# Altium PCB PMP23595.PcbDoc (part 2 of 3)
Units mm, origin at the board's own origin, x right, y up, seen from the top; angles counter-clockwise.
Board outline 121.92 x 78.74 mm, 6 copper layers (Layer 1, GND 1, Layer 3, Layer 4, GND 2, Layer 6), stack 2.208 mm thick; 236 components, 76 nets, 570 pads, 735 vias.
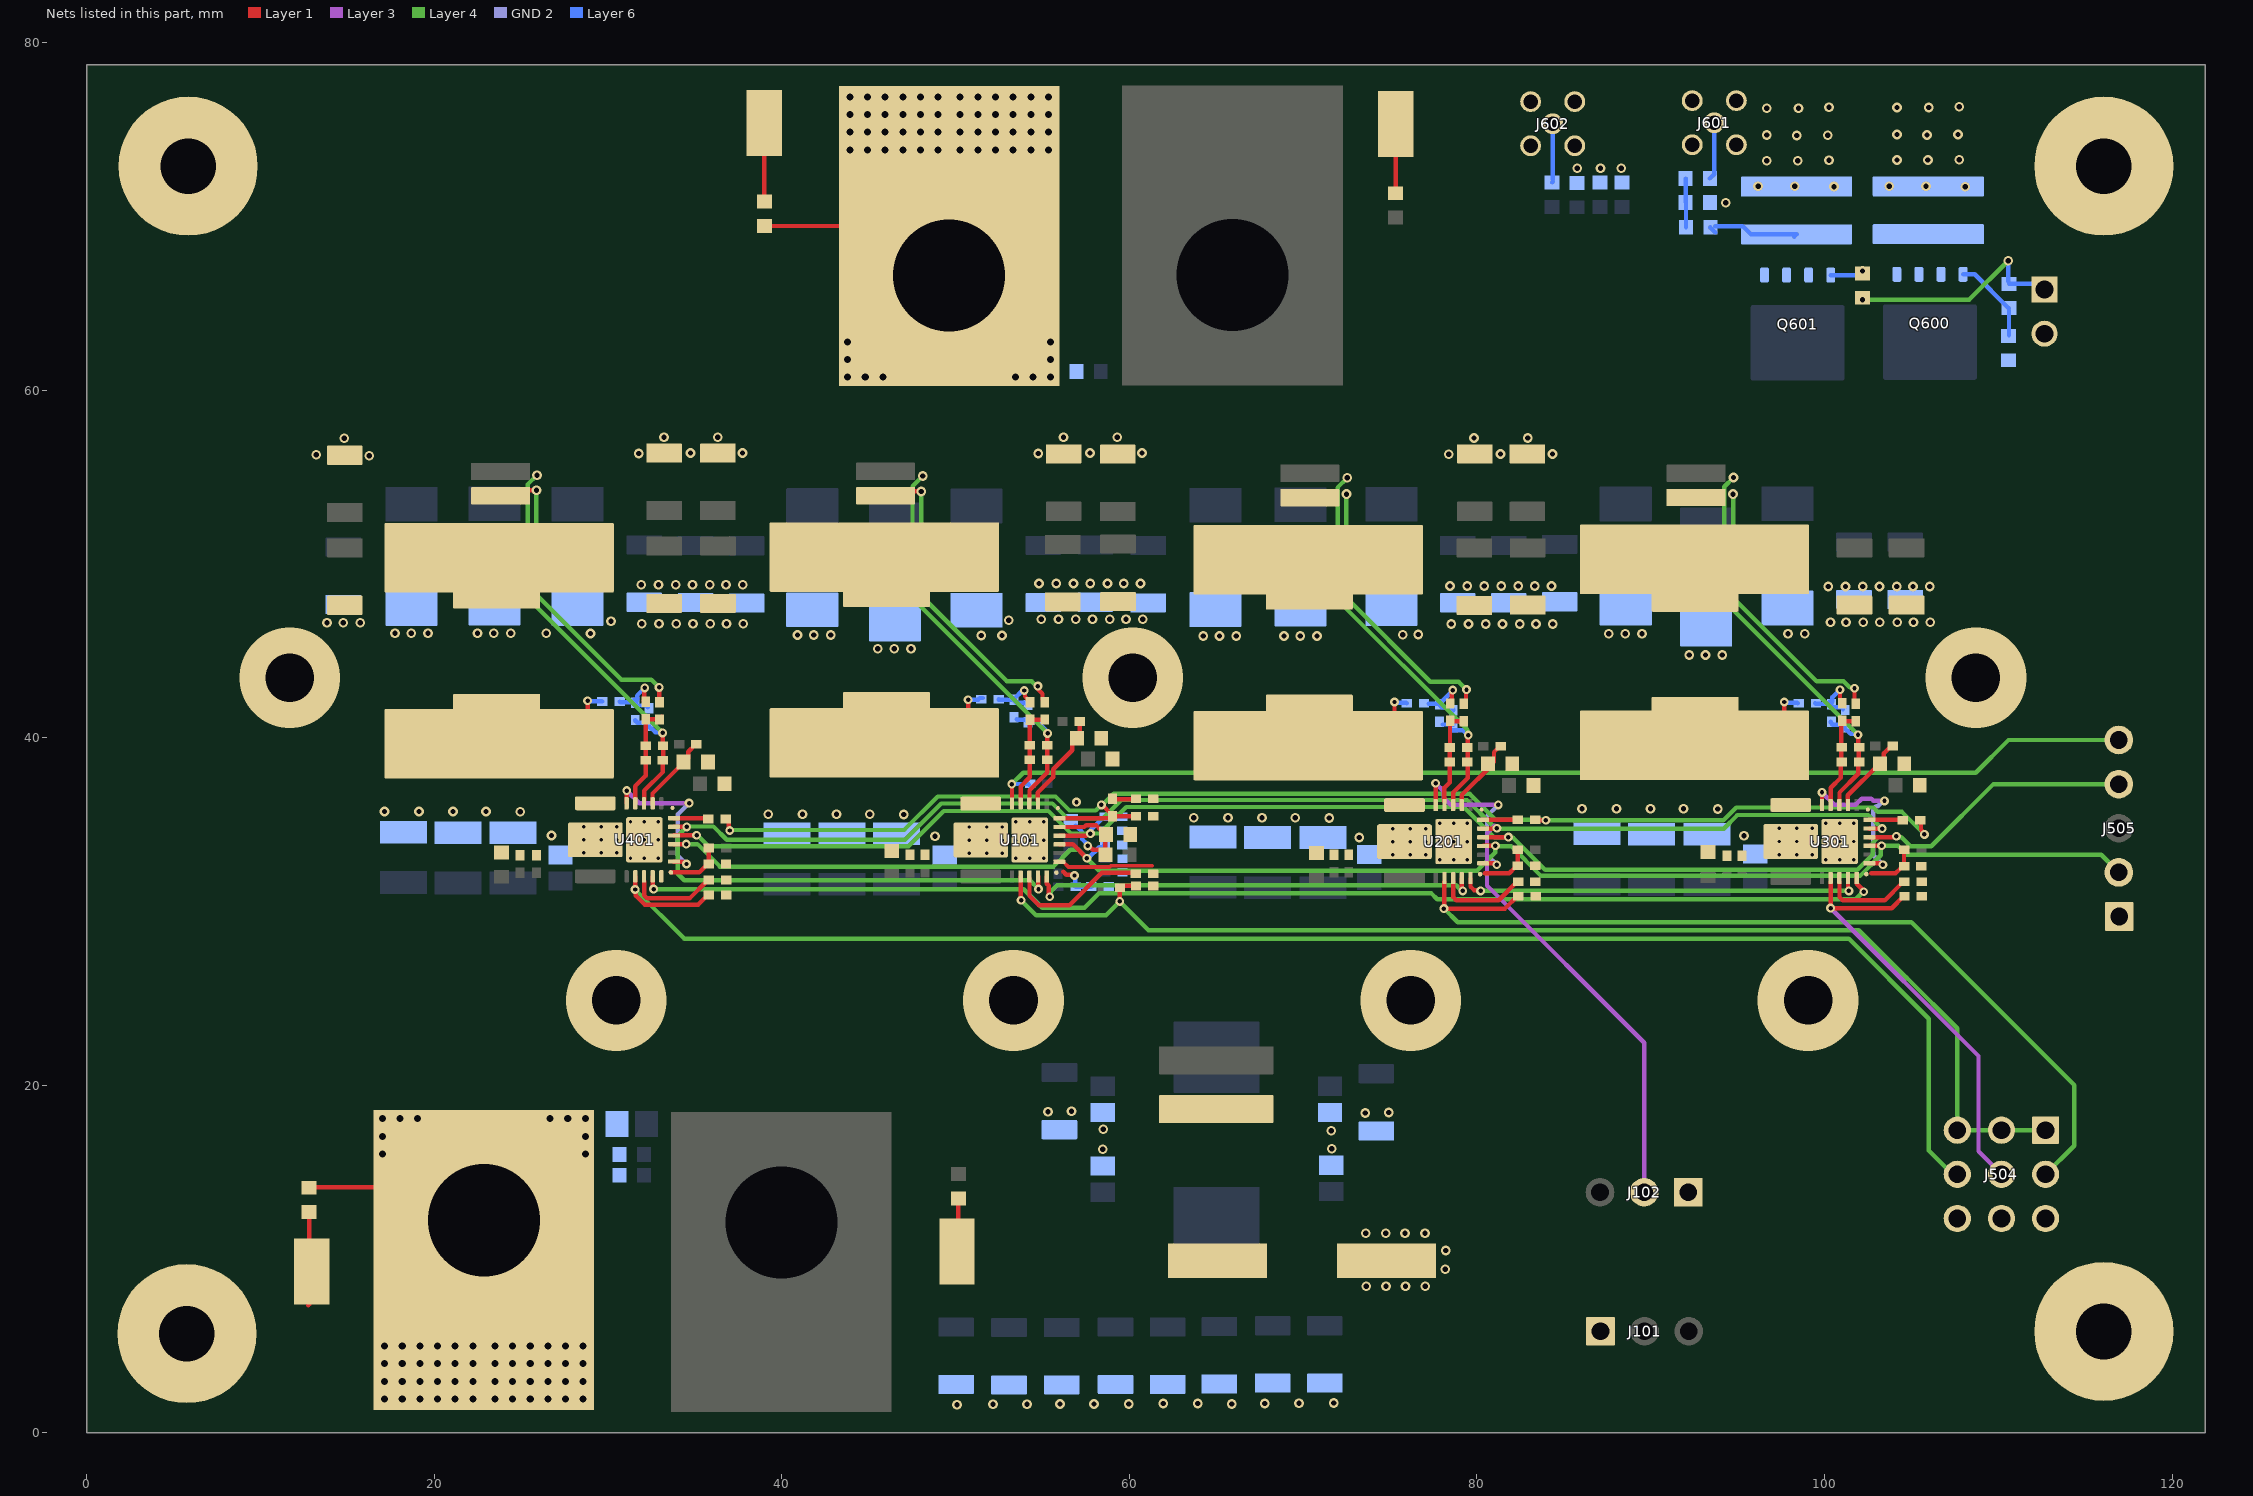
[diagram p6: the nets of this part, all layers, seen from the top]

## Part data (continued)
C123: library part CMP-0006310-1, "CAP, CERM, 150 pF, 50 V, +/- 5%, C0G/NP0, AEC-Q200 Grade 1, 0402", Cap_Case=0402, Manufacturer=TDK, Supplier Part Number 1=445-5598-1-ND, TempCo=C0G/NP0, Tolerance_%=5%, Value1=Unknown, Value2=50V, ValueDisplayed=150pF
C124: library part CMP-0006338-2, "CAP, CERM, 6800 pF, 100 V, +/- 10%, X7S, AEC-Q200 Grade 1, 0402", Cap_Case=0402, Manufacturer=TDK, Supplier Part Number 1=445-6909-1-ND, TempCo=X7S, Tolerance_%=10%, Value1="0.523223 ohm", Value2=100V, ValueDisplayed=6800pF
C223 C323 C423: library part CMP-0006312-1, "CAP, CERM, 47 pF, 50 V, +/- 5%, C0G/NP0, AEC-Q200 Grade 0, 0402", Cap_Case=0402, Manufacturer=TDK, Supplier Part Number 1=445-12142-1-ND, TempCo=C0G/NP0, Tolerance_%=5%, Value1=Unknown, Value2=50V, ValueDisplayed=47pF
C500 C601: library part CMP-0007468-5, "CAP, CERM, 0.01 uF, 100 V, +/- 10%, X7R, 0603", Cap_Case=0603, Manufacturer=MuRata, Supplier Part Number 1=GRM188R72A103KA01D-ND, TempCo=X7R, Tolerance_%=10%, Value1=Unknown, Value2=100V, ValueDisplayed=0.01uF
C501 C600: library part CMP-0007081-4, "CAP, CERM, 1000 pF, 100 V, +/- 10%, X7R, AEC-Q200 Grade 1, 0603", Cap_Case=0603, Manufacturer=TDK, Supplier Part Number 1=445-5806-1-ND, TempCo=X7R, Tolerance_%=10%, Value1="1.97137 ohm", Value2=100V, ValueDisplayed=1000pF
C502: library part CMP-0007722-2, "CAP, CERM, 0.1 uF, 100 V, +/- 10%, X7R, 0805", Cap_Case=0805, Manufacturer=Kemet, Supplier Part Number 1=399-3486-1-ND, TempCo=X7R, Tolerance_%=10%, Value1="0.064 ohm", Value2=100V, ValueDisplayed=0.1uF
C503 C504 C505 C506 C507 C508 C509 C510 C515 C516: library part CMP-0093675-1, "4.7uF ±10% 100V Ceramic Capacitor X7S 1210 (3225 Metric)", Manufacturer=Murata, Operating Temperature Range="-55°C to +125°C", TempCo=22%, Temperature Characteristic=X7S, Tolerance_%=10%, ValueDisplayed=4.7uF
C511 C512 C513 C514: library part CMP-0008374-2, "CAP, CERM, 0.47 uF, 100 V, +/- 10%, X7R, 0805", Cap_Case=0805, Manufacturer=MuRata, Supplier Part Number 1=490-3326-1-ND, TempCo=X7R, Tolerance_%=10%, Value1=Unknown, Value2=100V, ValueDisplayed=0.47uF
C517: library part CMP-0011216-2, "CAP, AL, 100 uF, 80 V, +/- 20%, 0.32 ohm, AEC-Q200 Grade 2, SMD", Cap_Case=H13, Manufacturer=Panasonic, Supplier Part Number 1=PCE3493CT-ND, Tolerance_%=20%, Value1="0.32 ohm", Value2=80V, ValueDisplayed=100uF
C518: library part CMP-0079095-1, "CAP, CERM, 0.1 µF, 50 V,+/- 10%, X7R, AEC-Q200 Grade 1, 0603", Cap_Case=0603, Manufacturer=AVX, Supplier Part Number 1=478-3540-1-ND, TempCo=X7R, Tolerance_%=10%, Value2=50V, ValueDisplayed=0.1µF
C602 C603: library part CMP-0007077-5, "CAP, CERM, 0.1 uF, 25 V, +/- 10%, X7R, AEC-Q200 Grade 1, 0603", Cap_Case=0603, Manufacturer=TDK, Supplier Part Number 1=445-5667-1-ND, TempCo=X7R, Tolerance_%=10%, Value1=Unknown, Value2=25V, ValueDisplayed=0.1uF
H700 H701 H702 H703: library part CMP-0003617-1, "Machine Screw, Round, #4-40 x 1/4, Nylon, Philips panhead", Manufacturer="B&F Fastener Supply", Supplier Part Number 1=H542-ND
H704 H705 H706 H707: library part CMP-0003611-1, "Standoff, Hex, 1\"L #4-40 Nylon", Manufacturer=Keystone, Supplier Part Number 1=36-1902E-ND
J101 J102: library part CMP-0075484-1, "Header, 100mil, 3x1, Gold, TH", Manufacturer=Samtec, Supplier Part Number 1=HTSW-103-07-G-S-ND
J504: library part CMP-0090263-1, "Connector Header Through Hole 9 position 0.100\" (2.54mm)", Digikey Part Number=SAM10328-ND, Manufacturer=Samtec, Mouser Part Number=200-TSW10307GT, Operating Temperature Range="-55°C to +125°C"
J505: library part CMP-0075411-1, "Header, 100mil, 5x1, Gold, TH", Color=Black, Current_A=6.3A, Manufacturer=Samtec, Supplier Part Number 1=SAM1029-05-ND, Voltage_V=550V
J600: library part CMP-0054947-1, "Header, 100mil, 2x1, Gold, TH", Manufacturer="TE Connectivity"
J601 J602: library part CMP-0075554-1, "Connector, MMCX 50 ohm, TH", Manufacturer=Samtec, Supplier Part Number 1=88K0549
L101 L201 L301 L401: library part CMP-0123970-1, "Power Choke Coil 4.7uH 20% 100kHz 4.7mOhm 27A AECQ200 13.3x12.8x8.0mm SMT", Manufacturer=Cyntec, Operating Temperature Range="-55°C to +180°C", Test Frequency=100kHz, Tolerance_%=20%
L500: library part CMP-0086238-1, "Inductor, 1 µH, 30 A, 0.00276 ohm, AEC-Q200 Grade 0, SMD", Manufacturer=Cyntec, Value1="0.00276 ohm", Value2=30A, ValueDisplayed=1µH
La101 La201 La301 La401: library part CMP-0122346-1, "IND SMD 4.7UH AUTO GRADE CHOKE", Digikey Part Number=2037-VCHA105D-4R7MS6CT-ND, Manufacturer=Cyntec, Operating Temperature Range="-55°C to +165°C", Test Frequency=100kHz, Tolerance_%=20%
Logo700: library part CMP-0074844-1
Logo701: library part CMP-0074838-1, "Texas Instrument Corporate Signature"
Logo702: library part CMP-0074847-1, "FCC_disclaimer"
Logo703: library part CMP-0074769-1
Logo704: library part CMP-0074837-2, "IEC 61010-1 Hot Surface Warning", Manufacturer="Texas Instruments"
NT21 NT31 NT41 NT101: library part CMP-0078142-4, "Single point connection between nets.", Manufacturer=N/A
Q600 Q601: library part CMP-0000584-2, "MOSFET, N-CH, 30 V, 51 A, DNK0008A (VSON-CLIP-8)", Alternate Manufacturer=None, Manufacturer="Texas Instruments", Value1=0.007, Value2="97 nC"
R101 R201 R301 R401: library part CMP-0124890-1, "1 mOhms ±5% 1.5W Chip Resistor Wide 1206 (3216 Metric), 0612 Automotive AEC-Q200, Current Sense Metal Foil", Digikey Part Number=408-KRL3216E-C-R001-J-T5CT-ND, Manufacturer=Susumu, Mouser Part Number=754-KRL3216ECR001JT5, Operating Temperature Range="-55°C to +175°C", Power_W=1.5W, TempCo=150ppm/°C, Tolerance_%=5%
R102: library part CMP-0078779-1, "RES, 10.0 k, 1%, 0.2 W, AEC-Q200 Grade 0, 0402", Manufacturer=Panasonic, Power_W=200mW, Supplier Part Number 1=P17230CT-ND, TempCo="100 ppm/C", Tolerance_%=1%, Value2=0.2W, Value_Code=10k0, ValueDisplayed=10.0k
R103 R105 R203 R205 R303 R305 R403 R405 R505 R506 R507: library part CMP-0027007-2, "RES, 0, 5%, 0.063 W, AEC-Q200 Grade 0, 0402", Manufacturer="KOA Speer", Power_W=63mW, Supplier Part Number 1=660-RK73Z1ETTP, TempCo=ppm/C, Tolerance_%=5%, Value2=0.063W, Value_Code=0000, ValueDisplayed=0
R104 R121 R204 R304 R404: library part CMP-0026748-1, "RES, 10.0 k, 1%, 0.063 W, AEC-Q200 Grade 0, 0402", Manufacturer="KOA Speer", Power_W=63mW, Supplier Part Number 1=660-RK73H1ETTP1002F, TempCo="100 ppm/C", Tolerance_%=1%, Value2=0.063W, Value_Code=10k0, ValueDisplayed=10.0k
R106: library part CMP-0026761-1, "RES, 49.9, 1%, 0.063 W, AEC-Q200 Grade 0, 0402", Manufacturer="Stackpole Electronics Inc", Power_W=63mW, Supplier Part Number 1=RMCF0402FT49R9CT-ND, TempCo="100 ppm/C", Tolerance_%=1%, Value2=0.063W, Value_Code=49R9, ValueDisplayed=49.9
R107 R208 R308 R408: library part CMP-0026823-3, "RES, 100 k, 5%, 0.063 W, AEC-Q200 Grade 0, 0402", Manufacturer=Vishay-Dale, Power_W=63mW, Supplier Part Number 1=541-100KJCT-ND, TempCo="200 ppm/C", Tolerance_%=5%, Value2=0.063W, Value_Code=100k
R108 R110 R207 R210 R307 R310 R407 R410: library part CMP-0026449-2, "RES, 54.9 k, 1%, 0.063 W, AEC-Q200 Grade 0, 0402", Manufacturer=Vishay-Dale, Power_W=63mW, Supplier Part Number 1=541-54.9KLCT-ND, TempCo="100 ppm/C", Tolerance_%=1%, Value2=0.063W, Value_Code=54k9, ValueDisplayed=54.9k
R109 R209 R309 R409: library part CMP-0026213-2, "RES, 27.4 k, 1%, 0.063 W, AEC-Q200 Grade 0, 0402", Manufacturer=Vishay-Dale, Power_W=63mW, Supplier Part Number 1=541-27.4KLCT-ND, TempCo="100 ppm/C", Tolerance_%=1%, Value2=0.063W, Value_Code=27k4, ValueDisplayed=27.4k
R111: library part CMP-0026873-2, "RES, 200 k, 5%, 0.063 W, AEC-Q200 Grade 0, 0402", Manufacturer=Vishay-Dale, Power_W=63mW, Supplier Part Number 1=541-200KJCT-ND, TempCo="200 ppm/C", Tolerance_%=5%, Value2=0.063W, Value_Code=200k
R112: library part CMP-0026337-2, "RES, 3.65 k, 1%, 0.063 W, AEC-Q200 Grade 0, 0402", Manufacturer=Vishay-Dale, Power_W=63mW, Supplier Part Number 1=541-3.65KLCT-ND, TempCo="100 ppm/C", Tolerance_%=1%, Value2=0.063W, Value_Code=3k65, ValueDisplayed=3.65k
R113: library part CMP-0026764-1, "RES, 10.0, 1%, 0.063 W, AEC-Q200 Grade 0, 0402", Manufacturer="Stackpole Electronics Inc", Power_W=63mW, Supplier Part Number 1=RMCF0402JT10R0CT-ND, TempCo="100 ppm/C", Tolerance_%=1%, Value2=0.063W, Value_Code=10R0, ValueDisplayed=10.0
R114: library part CMP-0026840-2, "RES, 150 k, 5%, 0.063 W, AEC-Q200 Grade 0, 0402", Manufacturer=Vishay-Dale, Power_W=63mW, Supplier Part Number 1=541-150KJCT-ND, TempCo="200 ppm/C", Tolerance_%=5%, Value2=0.063W, Value_Code=150k
R115 R202 R302 R402: library part CMP-0026622-3, "RES, 9.76 k, 1%, 0.063 W, AEC-Q200 Grade 0, 0402", Manufacturer=Vishay-Dale, Power_W=63mW, Supplier Part Number 1=541-9.76KLCT-ND, TempCo="100 ppm/C", Tolerance_%=1%, Value2=0.063W, Value_Code=9k76, ValueDisplayed=9.76k
R116: library part CMP-0026512-2, "RES, 6.04 k, 1%, 0.063 W, AEC-Q200 Grade 0, 0402", Manufacturer=Vishay-Dale, Power_W=63mW, Supplier Part Number 1=541-6.04KLCT-ND, TempCo="100 ppm/C", Tolerance_%=1%, Value2=0.063W, Value_Code=6k04, ValueDisplayed=6.04k
R117: library part CMP-0026518-2, "RES, 6.98 k, 1%, 0.063 W, AEC-Q200 Grade 0, 0402", Manufacturer=Vishay-Dale, Power_W=63mW, Supplier Part Number 1=541-6.98KLCT-ND, TempCo="100 ppm/C", Tolerance_%=1%, Value2=0.063W, Value_Code=6k98, ValueDisplayed=6.98k
R118: library part CMP-0084244-1, "RES, 1.0 k, 5%, 0.25 W, AEC-Q200 Grade 0, 0603", Manufacturer=Rohm, Power_W=250mW, TempCo="200 ppm/C", Tolerance_%=5%, Value2=0.25W, Value_Code=1k00, ValueDisplayed=1.0k
R119: library part CMP-0021990-4, "RES, 100 k, 1%, 0.1 W, AEC-Q200 Grade 0, 0603", Manufacturer=Vishay-Dale, Power_W=100mW, Supplier Part Number 1=541-100KHCT-ND, TempCo="100 ppm/C", Tolerance_%=1%, Value2=0.1W, Value_Code=100k
R120: library part CMP-0022665-4, "RES, 9.09 k, 1%, 0.1 W, AEC-Q200 Grade 0, 0603", Manufacturer=Vishay-Dale, Power_W=100mW, Supplier Part Number 1=541-9.09KHCT-ND, TempCo="100 ppm/C", Tolerance_%=1%, Value2=0.1W, Value_Code=9k09, ValueDisplayed=9.09k
R206 R306 R406: library part CMP-0026194-2, "RES, 249, 1%, 0.063 W, AEC-Q200 Grade 0, 0402", Manufacturer=Vishay-Dale, Power_W=63mW, Supplier Part Number 1=541-249LCT-ND, TempCo="100 ppm/C", Tolerance_%=1%, Value2=0.063W, Value_Code=249R, ValueDisplayed=249
R500 R501 R503 R504 R607: library part CMP-0022170-4, "RES, 1.00, 1%, 0.1 W, AEC-Q200 Grade 0, 0603", Manufacturer=Vishay-Dale, Power_W=100mW, Supplier Part Number 1=52K8059, TempCo="100 ppm/C", Tolerance_%=1%, Value2=0.1W, Value_Code=1R00, ValueDisplayed=1.00
R502: library part CMP-0084352-2, "1 Ohms ±1% 2W Chip Resistor Wide 2512 (6432 Metric), 1225 Automotive AEC-Q200 Thick Film", Digikey Part Number=RCL1.00ECT-ND, Manufacturer="Vishay Dale", Mouser Part Number=71-RCL12251R00FKEG, Operating Temperature Range="-55°C to +155°C", Power_W=2W, TempCo=100ppm/°C, Tolerance_%=1%
R600 R601: library part CMP-0025743-4, "RES, 1.0, 5%, 0.1 W, AEC-Q200 Grade 0, 0603", Manufacturer=Vishay-Dale, Power_W=100mW, Supplier Part Number 1=541-1.0GCT-ND, TempCo="200 ppm/C", Tolerance_%=5%, Value2=0.1W, Value_Code=1R00, ValueDisplayed=1.0
R602: library part CMP-0021998-4, "RES, 10.0 k, 1%, 0.1 W, AEC-Q200 Grade 0, 0603", Manufacturer=Vishay-Dale, Power_W=100mW, Supplier Part Number 1=541-10.0KHCT-ND, TempCo="100 ppm/C", Tolerance_%=1%, Value2=0.1W, Value_Code=10k0, ValueDisplayed=10.0k
R603 R604: library part CMP-0022448-4, "RES, 49.9, 1%, 0.1 W, AEC-Q200 Grade 0, 0603", Manufacturer=Vishay-Dale, Power_W=100mW, Supplier Part Number 1=541-49.9HCT-ND, TempCo="100 ppm/C", Tolerance_%=1%, Value2=0.1W, Value_Code=49R9, ValueDisplayed=49.9
R605 R606: library part CMP-0124591-1, "200 mOhms ±1% 1.5W Chip Resistor Wide 2512 (6432 Metric), 1225 Automotive AEC-Q200, Moisture Resistant Thick Film", Digikey Part Number=2019-WK73S3ATTER200FCT-ND, Manufacturer="KOA Speer", Mouser Part Number=660-WK73S3ATTER200F, Operating Temperature Range="-55°C to +155°C", Power_W=1.5W, TempCo=200ppm/°C, Tolerance_%=1%
SH-J700 SH-J701 SH-J702 SH-J703: library part CMP-0078738-1, "Single Operation 2.54mm Pitch Open Top Jumper Socket", Manufacturer=Harwin, Supplier Part Number 1=952-2881-ND
T500 T501 T502 T503: library part CMP-0055443-2, "Terminal 90A Lug", Manufacturer=Panduit, Supplier Part Number 1=CB70-14-CY-ND, Voltage_V=600V
TP500 TP501 TP502 TP503: library part CMP-0055162-1, "Test Point, Miniature, SMT", Manufacturer=Keystone, PartNumber=5019, Supplier Part Number 1=36-5019TR-ND
U101 U201 U301 U401: library part CMP-0125338-2, Manufacturer="Texas Instruments", Operating Temperature Range=to
ZZ700: library part CMP-0003616-3
ZZ701: library part CMP-0077236-1
ZZ702: library part CMP-0077237-1
ZZ703: library part CMP-0077238-1

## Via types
v1: diameter 0.559, hole 0.305, Layer 1 to Layer 6, tented both sides, 328 vias
v2: diameter 0.813, hole 0.406, Layer 1 to Layer 6, 232 vias
v3: diameter 0.508, hole 0.254, Layer 1 to Layer 6, tented both sides, 72 vias
v4: diameter 0.5, hole 0.2, Layer 1 to Layer 6, tented both sides, 72 vias
v5: diameter 0.559, hole 0.305, Layer 1 to Layer 6, 24 vias
v6: diameter 5.8, hole 2.8, Layer 1 to Layer 6, 7 vias

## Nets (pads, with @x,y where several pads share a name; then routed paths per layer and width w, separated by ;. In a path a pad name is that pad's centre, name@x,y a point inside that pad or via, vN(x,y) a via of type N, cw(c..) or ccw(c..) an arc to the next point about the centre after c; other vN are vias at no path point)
AGND1: C110.2 C123.2 C124.2 C125.2 C126.2 R110.1 R114.1 R115.1 R116.1 R117.1 R120.1 R121.1 U101.1 U101.16 | length 5.5
  Layer 1 w0.203: U101.16@55.975,32.87 56.2,32.87 56.501,32.569 58.873,32.569 58.943,32.639 61.316,32.639
  other v3: 56.96,36.301
AGND2: C210.2 C223.2 R208.1 R210.1 U201.1 U201.6 U201.16 | length 10.1
  Layer 1 w0.254: v3(77.622,37.389) 77.631,37.38 U201.6@77.631,36.351 ; U201.16@80.355,32.781 U201.16@80.358,32.778 80.988,32.779 81.076,32.69 v3@81.153,32.69
  Layer 3 w0.254: v3(77.622,37.389) 78.091,36.92 78.091,36.539 78.486,36.144 v3(81.229,36.144)
  GND 2 w0.254: v3(81.141,32.694) 80.583,33.252 80.583,35.498 81.153,36.068 v3@81.204,36.068
AGND3: C310.2 C323.2 R308.1 R310.1 U301.1 U301.6 U301.16 | length 10
  Layer 1 w0.254: U301.6@99.855,36.131 99.857,36.133 99.857,36.865 v3@99.873,36.881 ; U301.16@102.58,32.781 102.582,32.779 103.213,32.779 103.301,32.69 v3@103.378,32.69
  Layer 3 w0.254: v3@99.873,36.881 99.873,36.848 100.576,36.144 101.79,36.144 102.146,36.5 102.702,36.5 102.819,36.383 103.444,36.383 v3(103.454,36.373)
  GND 2 w0.254: v3(103.366,32.694) 102.808,33.252 102.808,35.879 102.988,36.059 103.072,36.059 103.385,36.373 v3(103.454,36.373)
  other v3: 99.86,36.86
AGND4: C410.2 C423.2 R408.1 R410.1 U401.1 U401.6 U401.16 | length 9.4
  Layer 1 w0.254: U401.6@31.072,36.232 31.074,36.234 31.074,36.967 v3@31.09,36.982 ; U401.16@33.797,32.882 33.799,32.88 34.31,32.88 34.45,32.741 v3(34.519,32.741)
  Layer 3 w0.254: v3@31.09,36.932 31.107,36.932 31.793,36.246 v3(34.671,36.246)
  GND 2 w0.254: v3(34.519,32.741) 34.025,33.234 34.025,35.6 34.646,36.22 v3@34.646,36.246
  other v3: 31.077,36.962
BIAS: C121.1 R103.1 U101.3 | length 5.3
  Layer 1 w0.254: U101.3@54.737,36.398 54.737,36.853 55.628,37.743 55.628,38.198 56.71,39.28 56.71,39.707 C121.1@56.983,39.98 ; C121.1@57.074,40.132 57.153,40.211 R103.1@57.153,40.915
BIAS2: C221.1 R203.1 U201.3 | length 4.1
  Layer 1 w0.254: U201.3@79.121,36.271 79.121,36.695 80.91,38.484 C221.1@80.91,38.509 ; C221.1@80.984,38.608 80.984,39.18 81.324,39.52 R203.1@81.374,39.52
BIAS3: C321.1 R303.1 U301.3 | length 4.3
  Layer 1 w0.254: U301.3@101.346,36.271 101.346,36.695 103.135,38.484 C321.1@103.135,38.509 ; C321.1@103.209,38.608 C321.1@103.408,38.807 ; C321.1@103.353,38.684 103.408,38.74 C321.1@103.408,38.807 ; R303.1@103.875,39.522 103.825,39.522 103.408,39.105 C321.1@103.408,38.807
BIAS4: C421.1 R403.1 U401.3 | length 4.3
  Layer 1 w0.254: U401.3@32.563,36.373 32.563,36.797 34.352,38.586 C421.1@34.352,38.611 ; C421.1@34.426,38.71 C421.1@34.625,38.909 ; C421.1@34.569,38.786 34.625,38.841 C421.1@34.625,38.909 ; R403.1@35.092,39.624 35.042,39.624 34.625,39.207 C421.1@34.625,38.909
COMP: C123.1 R112.2 R505.2 R506.2 R507.2 U101.21 | length 79.2
  Layer 1 w0.254: R507.2@36.771,35.331 36.821,35.331 36.944,35.208 36.944,34.803 37.008,34.74 v3(37.008,34.671) ; U101.21@55.975,35.37 58.829,35.37 59.004,35.546 59.004,35.567 58.427,36.144 v3(58.395,36.144) ; R112.2@59.03,35.492 C123.1@60.309,35.492 ; R505.2@83.382,35.255 83.395,35.268 83.96,35.268 v3(83.972,35.255) ; R506.2@105.554,35.23 105.554,34.714 105.753,34.516 v3(105.753,34.447)
  Layer 4 w0.254: v3(37.008,34.671) 37.033,34.696 47.041,34.696 48.971,36.627 55.753,36.627 56.56,35.82 58.071,35.82 v3(58.395,36.144) ; v3@58.463,36.144 59.098,36.779 79.578,36.779 81.062,35.296 83.932,35.296 v3(83.972,35.255) 94.186,35.255 94.922,35.992 102.819,35.992 103.073,35.738 104.462,35.738 v3@105.707,34.493
COMP2: R505.1 U201.21 | length 1.9
  Layer 1 w0.254: U201.21@80.358,35.278 80.359,35.28 82.193,35.28 R505.1@82.22,35.306
COMP3: R506.1 U301.21 | length 1.8
  Layer 1 w0.254: U301.21@102.583,35.285 102.585,35.283 104.366,35.283 R506.1@104.369,35.281
COMP4: R507.1 U401.21 | length 1.9
  Layer 1 w0.254: U401.21@33.797,35.382 33.799,35.38 35.613,35.38 R507.1@35.662,35.331
CSA: C122.1 R105.1 R106.1 R109.2 U101.5 | length 5.8
  Layer 1 w0.254: U101.5@53.746,36.322 53.746,37.203 54.274,37.731 C122.1@54.274,38.735 ; C122.1@54.229,38.684 54.274,38.729 C122.1@54.274,38.735 ; R109.2@54.254,39.624 54.277,39.646 54.277,41.048 R105.1@54.28,41.051 ; R109.2@54.274,39.573 C122.1@54.274,38.735 ; R105.1@54.28,41.072 54.299,41.053 R106.1@55.129,41.054 R106.1@55.129,41.054
CSA2: C222.1 R205.1 R206.1 R209.2 U201.5 | length 5.8
  Layer 1 w0.254: U201.5@78.13,36.354 78.13,37.124 78.435,37.429 78.435,38.583 78.448,38.595 R209.2@78.449,39.444 R209.2@78.449,39.444 ; R205.1@78.41,40.97 78.415,40.965 R205.1@78.455,40.965 ; R209.2@78.461,39.395 78.455,39.401 R205.1@78.455,40.965 ; R205.1@78.461,40.976 78.455,40.97 R205.1@78.455,40.965 ; R206.1@79.128,40.811 R206.1@79.251,40.934 ; R206.1@79.251,40.953 79.24,40.965 R205.1@78.455,40.965
CSA3: C322.1 R305.1 R306.1 R309.2 U301.5 | length 6
  Layer 1 w0.254: U301.5@100.355,36.354 100.355,37.124 100.948,37.716 C322.1@100.948,38.611 ; C322.1@100.889,38.633 100.962,38.706 100.962,39.483 R309.2@100.969,39.49 ; C322.1@100.962,38.662 C322.1@100.965,38.659 ; R305.1@100.962,40.978 100.969,40.971 R305.1@100.969,40.967 ; R309.2@100.965,39.421 100.969,39.425 R309.2@100.969,39.49 ; R305.1@100.965,40.97 R305.1@100.968,40.967 ; R309.2@100.976,39.497 R309.2@100.969,39.49 ; R306.1@101.875,41.129 101.752,41.006 101.752,40.956 101.741,40.967 R305.1@100.969,40.967 ; R309.2@100.969,39.49 R305.1@100.969,40.967
CSA4: C422.1 R405.1 R406.1 R409.2 U401.5 | length 6
  Layer 1 w0.254: U401.5@31.572,36.455 31.572,37.225 32.164,37.818 C422.1@32.164,38.712 ; C422.1@32.106,38.735 32.179,38.808 32.179,39.585 R409.2@32.186,39.592 ; C422.1@32.179,38.764 C422.1@32.182,38.76 ; R405.1@32.179,41.08 32.186,41.073 R405.1@32.186,41.069 ; R409.2@32.182,39.522 32.186,39.526 R409.2@32.186,39.592 ; R405.1@32.182,41.072 R405.1@32.185,41.069 ; R409.2@32.193,39.599 R409.2@32.186,39.592 ; R406.1@33.092,41.23 32.969,41.107 R406.1@32.969,41.057 32.958,41.069 R405.1@32.186,41.069 ; R409.2@32.186,39.592 R405.1@32.186,41.069
EN/UVLO: J504.1 J504.4 J504.7 R111.1 R117.2 U101.11 | length 71.7
  Layer 1 w0.254: U101.11@53.75,32.02 53.752,32.018 53.752,30.678 v3(53.772,30.658) ; v3@59.461,30.607 59.457,30.612 59.457,31.488 R111.1@59.465,31.496 ; R111.1@59.512,31.42 59.588,31.496 R117.2@60.384,31.496
  Layer 4 w0.254: v3(53.772,30.658) 54.635,29.794 58.657,29.794 v3@59.419,30.556 ; v3(59.449,30.586) 61.105,28.931 101.981,28.931 104.775,26.137 ; 104.75,26.187 107.645,23.292 J504.7@107.645,17.424 J504.4@110.185,17.424 J504.1@112.725,17.424
EN/UVLO2: C223.1 J504.2 U201.11 | length 52.4
  Layer 1 w0.254: U201.11@78.131,31.705 78.131,30.201 v3(78.105,30.175) 81.619,30.175 82.33,30.886 C223.1@82.372,30.886
  Layer 4 w0.254: v3(78.105,30.175) 78.892,29.388 105.004,29.388 114.371,20.02 114.371,16.531 J504.2@112.725,14.884
EN/UVLO3: C323.1 J504.5 U301.11 | length 25.4
  Layer 1 w0.254: U301.11@100.357,31.712 100.357,30.202 v3(100.355,30.201) 103.869,30.201 104.504,30.836 C323.1@104.546,30.836
  Layer 3 w0.254: v3(100.355,30.201) 108.864,21.692 108.864,16.205 J504.5@110.185,14.884
EN/UVLO4: C423.1 J504.8 U401.11 | length 92.7
  Layer 1 w0.254: v3(31.56,31.272) 31.608,31.223 31.608,30.908 32.111,30.405 35.189,30.405 35.721,30.937 C423.1@35.814,30.937 ; U401.11@31.572,32.032 31.57,32.03 31.57,31.346 v3@31.598,31.318
  Layer 4 w0.254: v3(31.56,31.272) 34.384,28.448 101.397,28.448 106.005,23.84 106.005,16.253 J504.8@107.344,14.914
FB1: R118.1 R119.1 R120.2 U101.20 | length 6.2
  Layer 1 w0.254: U101.20@55.975,34.87 57.414,34.87 57.522,34.979 58.087,34.979 58.355,34.71 58.603,34.71 R120.2@58.62,34.693 ; v3(57.607,33.782) 57.676,33.782 57.891,33.567 58.482,33.567 R118.1@58.522,33.528 ; R118.1@58.62,33.477 58.62,34.262 R120.2@58.725,34.366
  Layer 6 w0.254: R119.1@56.921,34.955 57.279,34.598 57.279,34.319 57.281,34.316 57.281,34.177 57.607,33.851 v3(57.607,33.782)
FPWM/SYNC1: J102.2 U101.13 U201.20 U301.20 U401.20 | length 124.2
  Layer 1 w0.254: U401.20@33.797,34.882 33.799,34.88 34.563,34.88 v3@34.569,34.874 ; v3@54.712,31.242 54.752,31.282 54.752,32.018 U101.13@54.75,32.02 ; U201.20@80.355,34.781 U201.20@80.358,34.778 80.359,34.78 81.135,34.78 v3(81.153,34.798) ; U301.20@102.58,34.781 102.582,34.779 103.347,34.779 v3@103.353,34.773
  Layer 3 w0.254: v3@81.026,34.95 80.583,34.508 80.583,31.501 89.624,22.46 J102.2@89.624,13.853
  Layer 4 w0.254: v3@34.451,34.84 34.451,34.793 34.011,34.353 34.011,32.182 34.392,31.801 54.272,31.801 v3(54.775,31.297) ; v3@34.519,34.9 34.52,34.898 36.07,34.898 36.83,34.138 47.092,34.138 49.174,36.22 55.575,36.22 56.413,35.382 58.496,35.382 59.538,36.424 79.433,36.424 80.915,34.942 80.941,34.942 81.084,34.798 v3(81.153,34.798) 81.177,34.774 94.205,34.774 94.994,35.562 102.529,35.562 v3(103.317,34.774)
  other v3: 34.534,34.876
FPWM/SYNC2: U101.14 U201.13 | length 26.3
  Layer 1 w0.254: U101.14@55.25,32.02 55.252,32.018 55.252,31.609 55.374,31.486 55.374,30.91 v3(55.423,30.861) ; v3@79.121,31.166 79.136,31.181 79.136,31.313 79.132,31.317 79.132,31.929 U201.13@79.13,31.931
  Layer 4 w0.254: v3(55.423,30.861) 55.471,30.91 55.471,31.153 55.84,31.521 78.807,31.521 79.133,31.196 v3(79.185,31.196)
FPWM/SYNC3: U201.14 U301.13 | length 23.1
  Layer 1 w0.254: U201.14@79.633,31.928 79.633,31.441 79.834,31.24 80.165,31.24 v3(80.213,31.191) ; v3@101.346,31.166 101.361,31.181 101.361,31.313 101.357,31.317 101.357,31.929 U301.13@101.355,31.931
  Layer 4 w0.254: v3(80.213,31.191) 80.216,31.194 101.407,31.194 v3(101.41,31.196)
FPWM/SYNC4: U301.14 U401.13 | length 72.5
  Layer 1 w0.254: v3@32.563,31.267 32.578,31.283 32.578,31.415 32.574,31.419 32.574,32.03 U401.13@32.572,32.032 ; U301.14@101.858,31.935 101.86,31.933 101.86,31.609 102.26,31.209 v3(102.26,31.14)
  Layer 4 w0.254: v3@32.639,31.242 32.694,31.297 52.599,31.297 ; 52.603,31.293 53.924,31.293 54.991,30.226 57.422,30.226 58.264,31.067 77.365,31.067 77.724,30.709 101.794,30.709 102.226,31.14 v3(102.26,31.14)
  other v3: 32.627,31.297
GND: C101.2 C102.2 C103.2 C104.2 C105.2 C106.2 C107.2 C111.2 C112.2 C113.2 C114.2 C115.2 C116.2 C117.2 C118.1 C119.1 C120.1 C121.2 C201.2 C202.2 C203.2 C204.2 C205.2 C206.2 C207.2 C211.2 C212.2 C213.2 C214.2 C215.2 C216.2 C217.2 C218.1 C219.1 C220.1 C221.2 C301.2 C302.2 C303.2 C304.2 C305.2 C306.2 C307.2 C311.2 C312.2 C313.2 C314.2 C315.2 C316.2 C317.2 C318.1 C319.1 C320.1 C321.2 C401.2 C402.2 C403.2 C404.2 C405.2 C406.2 C407.2 C411.2 C412.2 C413.2 C414.2 C415.2 C416.2 C417.2 C418.1 C419.1 C420.1 C421.2 C500.1 C501.2 C502.2 C503.1 C504.1 C505.1 C506.1 C507.1 C508.1 C509.1 C510.1 C511.2 C512.2 C513.2 C514.2 C515.1 C516.1 C517.2 C518.2 C600.2 C601.1 C602.1 C603.1 H700.1 H701.1 H702.1 H703.1 J101.1 J102.1 J504.3 J504.6 J504.9 J505.1 J600.2 J601.2 J601.3 J601.4 J601.5 J602.2 J602.3 J602.4 J602.5 R503.2 R504.1 R602.1 R605.1 R606.1 T502.1 T503.1 U101.8 U101.22 U201.8 U201.22 U301.8 U301.22 U401.8 U401.22 | length 21.8
  Layer 1 w0.254: R503.2@12.817,14.148 20.955,14.148 T502.1@22.86,12.243 ; R504.1@39.014,69.455 47.461,69.455 T503.1@49.225,67.691
  Layer 6 w0.254: v4@55.042,35.154 v4@55.042,35.168
  other v1: 50.087,1.631 52.152,1.648 54.108,1.648 57.973,1.663 56.013,1.673 59.976,1.673 65.894,1.673 61.957,1.699 63.938,1.699 67.799,1.699 69.759,1.713 71.761,1.724 73.632,8.438 74.775,8.438 75.893,8.438 77.036,8.438 78.179,9.429 78.204,10.495 73.607,11.486 74.75,11.486 75.868,11.486 77.011,11.486 58.471,16.332 71.653,16.36 71.628,17.399 58.494,17.48 73.584,18.415 74.93,18.44 55.321,18.491 56.667,18.517 73.228,34.265 48.819,34.341 95.372,34.373 26.745,34.385 71.504,35.391 63.702,35.401 65.684,35.401 67.639,35.401 69.544,35.401 47.019,35.594 39.217,35.605 41.198,35.605 43.154,35.605 45.059,35.605 24.946,35.746 17.144,35.757 19.125,35.757 21.081,35.757 22.986,35.757 86.051,35.922 88.032,35.922 89.988,35.922 91.893,35.922 93.852,35.911 92.213,44.769 93.153,44.769 94.118,44.769 45.532,45.125 46.472,45.125 47.437,45.125 64.252,45.855 65.192,45.855 66.157,45.855 68.9,45.855 69.84,45.855 70.805,45.855 51.476,45.887 52.669,45.887 40.909,45.913 41.849,45.913 42.814,45.913 75.733,45.931 76.631,45.948 28.998,46.008 87.59,45.988 88.53,45.988 89.495,45.988 97.903,45.988 98.868,45.988 17.744,46.014 18.684,46.014 19.649,46.014 22.494,46.014 23.434,46.014 24.399,46.014 26.443,46.013 78.527,46.548 79.517,46.548 80.508,46.548 81.473,46.548 82.464,46.548 83.403,46.548 84.369,46.548 31.943,46.573 32.934,46.573 33.924,46.573 34.889,46.573 35.88,46.573 36.82,46.573 37.785,46.573 13.833,46.617 14.773,46.617 15.738,46.617 100.345,46.649 101.234,46.649 102.225,46.649 103.19,46.649 104.181,46.649 105.12,46.649 106.086,46.649 30.175,46.711 53.069,46.774 54.93,46.827 55.921,46.827 56.911,46.827 57.876,46.827 58.867,46.827 59.807,46.827 60.772,46.827 100.218,48.707 101.209,48.707 102.199,48.707 103.165,48.707 104.155,48.707 105.095,48.707 106.06,48.707 78.45,48.732 79.441,48.732 80.432,48.732 81.397,48.732 82.387,48.732 83.327,48.732 84.292,48.732 31.918,48.808 32.908,48.808 33.899,48.808 34.864,48.808 35.855,48.808 36.794,48.808 37.76,48.808 54.803,48.885 55.794,48.885 56.784,48.885 57.749,48.885 58.74,48.885 59.68,48.885 60.645,48.885 16.262,56.235 13.214,56.286 78.384,56.312 81.356,56.337 84.353,56.337 31.775,56.363 54.762,56.363 34.747,56.388 37.744,56.388 57.734,56.388 60.731,56.388 14.833,57.245 79.832,57.252 82.931,57.252 33.223,57.302 36.322,57.302 56.21,57.302 59.309,57.302 94.326,70.791 85.772,72.781 87.119,72.781 88.312,72.781 96.678,73.208 98.456,73.208 100.259,73.234 104.174,73.246 105.952,73.246 107.756,73.271 98.405,74.656 96.672,74.685 100.183,74.681 105.901,74.694 104.169,74.723 107.679,74.719 96.678,76.231 98.506,76.231 100.259,76.282 104.174,76.269 106.003,76.269 107.756,76.319
  other v2: 17.145,1.956 18.161,1.956 19.177,1.956 20.193,1.956 21.209,1.956 22.225,1.956 23.495,1.956 24.511,1.956 25.527,1.956 26.543,1.956 27.559,1.956 28.575,1.956 17.145,2.972 18.161,2.972 19.177,2.972 20.193,2.972 21.209,2.972 22.225,2.972 23.495,2.972 24.511,2.972 25.527,2.972 26.543,2.972 27.559,2.972 28.575,2.972 17.145,3.988 18.161,3.988 19.177,3.988 20.193,3.988 21.209,3.988 22.225,3.988 23.495,3.988 24.511,3.988 25.527,3.988 26.543,3.988 27.559,3.988 28.575,3.988 17.145,5.004 18.161,5.004 19.177,5.004 20.193,5.004 21.209,5.004 22.225,5.004 23.495,5.004 24.511,5.004 25.527,5.004 26.543,5.004 27.559,5.004 28.575,5.004 17.018,16.053 28.702,16.053 17.018,17.069 28.702,17.069 17.018,18.085 18.034,18.085 19.05,18.085 26.67,18.085 27.686,18.085 28.702,18.085 43.79,60.757 44.806,60.757 45.822,60.757 53.442,60.757 54.458,60.757 55.474,60.757 43.79,61.773 55.474,61.773 43.79,62.789 55.474,62.789 43.917,73.838 44.933,73.838 45.949,73.838 46.965,73.838 47.981,73.838 48.997,73.838 50.267,73.838 51.283,73.838 52.299,73.838 53.315,73.838 54.331,73.838 55.347,73.838 43.917,74.854 44.933,74.854 45.949,74.854 46.965,74.854 47.981,74.854 48.997,74.854 50.267,74.854 51.283,74.854 52.299,74.854 53.315,74.854 54.331,74.854 55.347,74.854 43.917,75.87 44.933,75.87 45.949,75.87 46.965,75.87 47.981,75.87 48.997,75.87 50.267,75.87 51.283,75.87 52.299,75.87 53.315,75.87 54.331,75.87 55.347,75.87 43.917,76.886 44.933,76.886 45.949,76.886 46.965,76.886 47.981,76.886 48.997,76.886 50.267,76.886 51.283,76.886 52.299,76.886 53.315,76.886 54.331,76.886 55.347,76.886
  other v4: 77.858,32.978 78.658,32.978 79.458,32.978 100.083,32.985 100.883,32.985 101.683,32.985 31.297,33.082 32.097,33.082 32.897,33.082 53.475,33.07 54.275,33.07 55.075,33.07 75.168,33.278 76.168,33.278 77.068,33.278 97.393,33.285 98.393,33.285 99.293,33.285 28.607,33.382 29.607,33.382 30.507,33.382 50.785,33.37 51.785,33.37 52.685,33.37 75.168,34.028 76.168,34.028 77.068,34.028 77.858,34.028 78.658,34.028 79.458,34.028 97.393,34.035 98.393,34.035 99.293,34.035 100.083,34.035 100.883,34.035 101.683,34.035 50.785,34.12 51.785,34.12 52.685,34.12 53.475,34.12 54.275,34.12 55.075,34.12 28.607,34.132 29.607,34.132 30.507,34.132 31.297,34.132 32.097,34.132 32.897,34.132 75.168,34.778 76.168,34.778 77.068,34.778 97.393,34.785 98.393,34.785 99.293,34.785 28.607,34.882 29.607,34.882 30.507,34.882 50.785,34.87 51.785,34.87 52.685,34.87 77.858,35.078 78.658,35.078 79.458,35.078 100.083,35.085 100.883,35.085 101.683,35.085 31.297,35.182 32.097,35.182 32.897,35.182 53.475,35.17 54.275,35.17 55.075,35.17
  other v5: 108.1,71.713 100.546,71.72 103.736,71.742 105.845,71.742 96.182,71.749 98.29,71.749
  other v6: 30.48,24.892 53.34,24.892 76.2,24.892 99.06,24.892 11.684,43.459 60.198,43.459 108.712,43.459
IMON: C125.1 J505.2 R115.2 U101.18 U201.18 U301.18 U401.18 | length 93.6
  Layer 1 w0.254: U401.18@33.797,33.882 33.799,33.884 34.569,33.884 v3@34.595,33.858 ; U101.18@55.975,33.87 56.757,33.87 v3(57.556,33.071) ; U201.18@80.355,33.781 80.357,33.783 81.127,33.783 v3@81.153,33.757 ; U301.18@102.58,33.781 102.582,33.783 103.352,33.783 v3@103.378,33.757
  Layer 4 w0.254: v3@34.493,33.909 34.514,33.888 35.149,33.888 36.444,32.593 55.64,32.593 56.6,33.553 57.074,33.553 58.268,32.36 80.01,32.36 81.056,33.405 81.056,33.778 v3(81.064,33.787) 81.091,33.76 81.988,33.76 83.695,32.053 102.044,32.053 103.24,33.249 103.24,33.478 ; v3@34.506,33.819 v3(34.506,33.888) ; 103.241,33.478 103.241,33.738 v3(103.289,33.787) 104.237,33.787 104.75,33.274 115.923,33.274 J505.2@116.939,32.258
  Layer 6 w0.254: v3(57.556,33.071) 57.625,33.071 58.266,33.712 58.479,33.712 C125.1@58.602,33.835 ; C125.1@58.547,33.858 58.571,33.883 58.571,34.625 R115.2@58.592,34.646
ISET: J505.4 R114.2 U101.19 U201.19 U301.19 U401.19 | length 95.9
  Layer 1 w0.254: U401.19@33.797,34.382 33.799,34.384 35.095,34.384 v3(35.103,34.392) ; U101.19@55.975,34.37 57.526,34.37 57.6,34.445 57.711,34.445 v3(57.76,34.493) ; U201.19@80.358,34.278 80.36,34.28 81.804,34.28 v3(81.813,34.29) ; U301.19@102.583,34.285 104.016,34.285 104.071,34.341 v3(104.14,34.341)
  Layer 4 w0.254: v3(35.103,34.392) 35.146,34.392 35.783,33.755 47.293,33.755 49.327,35.789 55.347,35.789 56.642,34.493 v3(57.76,34.493) 57.764,34.498 58.298,34.498 59.82,36.02 79.245,36.02 80.998,34.268 81.791,34.268 v3(81.813,34.29) 81.862,34.241 82.091,34.241 83.925,32.407 101.897,32.407 102.768,33.278 102.768,33.946 103.116,34.293 104.093,34.293 v3(104.14,34.341) 104.189,34.292 104.417,34.292 104.953,33.757 106.147,33.757 109.728,37.338 J505.4@116.939,37.338
  Layer 6 w0.254: v3(57.76,34.493) 57.808,34.542 57.808,34.733 58.41,35.335 58.475,35.335 R114.2@58.496,35.357
NetC109_1: C109.1 R102.2 R104.2 R105.2 | length 3.4
  Layer 1 w0.254: v3(53.95,42.723) 53.998,42.674 53.998,42.383 54.246,42.136 R105.2@54.251,42.136
  Layer 6 w0.254: R102.2@52.48,42.215 52.496,42.198 C109.1@53.365,42.198 ; v3(53.95,42.723) 53.901,42.674 53.808,42.674 53.365,42.231 53.365,42.131 53.488,42.008 54.056,42.008 R104.2@54.174,41.891
NetC109_2: C109.2 C122.2 NT101.1 R104.1 R109.1 U101.4 | length 25.1
  Layer 1 w0.254: U101.4@54.254,36.373 54.254,36.983 55.274,38.002 C122.2@55.274,38.633 ; C122.2@55.101,38.612 55.122,38.633 C122.2@55.274,38.633 ; C122.2@55.245,38.71 55.274,38.738 R109.1@55.274,39.573 ; R109.1@55.245,39.599 55.285,39.638 55.285,40.248 v3(55.296,40.259) ; C122.2@55.274,38.735 C122.2@55.274,38.633 ; C122.2@55.296,38.633 C122.2@55.274,38.633
  Layer 4 w0.254: v1(48.108,55.067) 47.525,54.485 47.525,48.03 55.27,40.284 v3@55.27,40.234
  Layer 6 w0.254: C109.2@53.518,41.072 53.543,41.047 54.051,41.047 54.174,40.924 R104.1@54.174,40.891 54.74,40.891 55.247,40.384 55.247,40.308 v3(55.296,40.259) ; R104.1@54.17,40.945 R104.1@54.204,40.945 ; R104.1@54.25,40.762 R104.1@54.25,40.815
NetC124_1: C124.1 R112.1 | length 1.2
  Layer 1 w0.254: R112.1@59.129,36.474 C124.1@60.285,36.474
NetC209_1: C209.1 R202.2 R204.2 R205.2 | length 3.4
  Layer 1 w0.254: R205.2@78.461,41.976 78.564,42.08 78.564,42.7 v3(78.613,42.748)
  Layer 6 w0.254: R202.2@77.229,41.957 77.82,41.957 C209.1@77.854,41.922 ; C209.1@77.854,41.891 77.977,41.768 78.521,41.768 78.644,41.645 R204.2@78.644,41.595 ; C209.1@77.977,42.075 78.613,42.711 v3(78.613,42.748)
NetC209_2: C209.2 C222.2 NT21.1 R204.1 R209.1 U201.4 | length 23.9
  Layer 1 w0.254: U201.4@78.638,36.297 78.638,36.85 79.477,37.688 C222.2@79.477,38.621 ; C222.2@79.478,38.742 79.478,39.565 79.475,39.567 79.475,40.131 v3(79.502,40.157)
  Layer 4 w0.254: v1(72.549,54.965) 71.985,54.401 71.985,47.928 79.453,40.46 79.453,40.206 v3(79.502,40.157)
  Layer 6 w0.254: C209.2@78.031,40.768 78.637,40.768 R204.1@78.644,40.761 ; R204.1@78.577,40.437 79.204,40.437 79.484,40.157 v3(79.502,40.157)
NetC309_1: C309.1 R302.2 R304.2 R305.2 | length 3.7
  Layer 1 w0.254: v3(100.897,42.77) 100.897,42.102 R305.2@101.016,41.983
  Layer 6 w0.254: R302.2@99.458,41.989 99.491,41.957 100.385,41.957 C309.1@100.406,41.935 ; C309.1@100.305,42.088 100.447,42.088 100.457,42.098 100.457,42.33 v3(100.897,42.77) ; C309.1@100.355,41.925 100.355,41.884 100.478,41.761 101.023,41.761 101.067,41.717 R304.2@101.067,41.656
NetC309_2: C309.2 C322.2 NT31.1 R304.1 R309.1 U301.4 | length 24.5
  Layer 1 w0.254: U301.4@100.863,36.297 100.863,36.85 101.948,37.934 C322.2@101.948,38.611 ; R309.1@101.905,39.421 101.947,39.463 101.94,39.469 101.94,40.173 v3(101.93,40.183) ; v3@101.947,40.166 v3@101.979,40.134 ; R309.1@101.976,39.497 101.962,39.483 101.962,38.754 C322.2@101.981,38.735
  Layer 4 w0.254: v1(94.767,54.976) 94.236,54.444 94.236,47.877 101.905,40.208 v3@101.981,40.208
  Layer 6 w0.254: C309.2@100.355,40.925 100.355,40.884 100.478,40.761 101.111,40.761 R304.1@101.117,40.767 ; R304.1@101.146,40.597 101.146,40.547 101.269,40.424 101.319,40.424 101.511,40.231 101.882,40.231 v3(101.93,40.183) v3@101.981,40.132
NetC409_1: C409.1 R402.2 R404.2 R405.2 | length 3.6
  Layer 1 w0.254: R405.2@32.055,42.139 32.088,42.172 v3@32.088,42.82
  Layer 6 w0.254: R402.2@30.675,42.091 30.707,42.058 31.602,42.058 C409.1@31.623,42.037 ; C409.1@31.521,42.189 31.664,42.189 31.674,42.199 31.674,42.431 v3(32.114,42.871) ; C409.1@31.572,42.026 31.572,41.985 31.695,41.862 32.239,41.862 32.283,41.818 R404.2@32.283,41.758
NetC409_2: C409.2 C422.2 NT41.1 R404.1 R409.1 U401.4 | length 24.6
  Layer 1 w0.254: U401.4@32.08,36.398 32.08,36.952 33.164,38.036 C422.2@33.164,38.712 ; R409.1@33.122,39.522 33.164,39.564 33.157,39.571 33.157,40.274 v3(33.147,40.284) ; v3@33.164,40.268 v3@33.196,40.236 ; R409.1@33.193,39.599 33.179,39.585 33.179,38.856 C422.2@33.198,38.837
  Layer 4 w0.254: v1(25.914,55.117) 25.376,54.579 25.376,48.055 v3(33.147,40.284)
  Layer 6 w0.254: C409.2@31.572,41.026 31.572,40.985 31.695,40.862 32.328,40.862 R404.1@32.334,40.869 ; R404.1@32.362,40.699 32.362,40.649 32.485,40.526 32.535,40.526 32.728,40.333 33.098,40.333 v3(33.147,40.284) v3@33.198,40.234
NetC517_1: C517.1 R502.1
NetC602_2: C602.2 R603.1 R607.1 | length 2.8
  Layer 6 w0.254: R603.1@92.007,72.185 92.013,72.179 C602.2@92.013,70.811 92.033,70.79 R607.1@92.033,69.38
NetJ600_1: J600.1 R600.2 R601.1 | length 13.3
  Layer 4 w0.254: v1(102.189,65.202) 108.32,65.202 v1(110.571,67.452)
  Layer 6 w0.254: v1@110.543,67.508 110.571,67.481 v1(110.571,67.452) 110.571,66.274 R600.2@110.619,66.225 ; R600.2@110.619,66.125 112.356,66.125 J600.1@112.928,65.553 ; J600.1@112.61,65.499 J600.1@112.61,65.647
NetJ601_1: J601.1 R603.2 | length 3.3
  Layer 6 w0.254: R603.2@93.407,72.185 93.659,72.437 J601.1@93.659,75.398
NetJ602_1: J602.1 R604.1 | length 3.4
  Layer 6 w0.254: R604.1@84.328,71.955 R604.1@84.362,71.989 ; R604.1@84.362,72.116 J602.1@84.362,75.339 84.362,75.396 J602.1@84.404,75.438
NetL101_2: L101.2 La101.2 R101.1 R106.2 | length 16.5
  Layer 1 w0.254: R101.1@47.346,54.229 47.396,54.178 v1(48.031,54.178) ; v3@54.686,42.926 54.686,42.857 55.006,42.537 55.006,42.2 R106.2@55.093,42.113
  Layer 4 w0.254: v1(48.031,54.178) 48.031,48.184 52.959,43.256 54.376,43.256 54.528,43.104 54.541,43.104 54.668,42.977 v3(54.737,42.977)
NetL201_2: L201.2 La201.2 R201.1 R206.2 | length 15.9
  Layer 1 w0.254: R206.2@79.251,41.953 79.374,42.076 79.374,42.274 79.375,42.275 v3@79.375,42.723
  Layer 4 w0.254: v1(72.492,54.026) 72.492,48.057 77.319,43.229 78.945,43.229 v3(79.4,42.774)
NetL301_2: L301.2 La301.2 R301.1 R306.2 | length 16
  Layer 1 w0.254: v3(101.727,42.85) 101.727,42.04 R306.2@101.806,41.96
  Layer 4 w0.254: v1(94.742,54.026) 94.742,48.057 99.548,43.251 101.096,43.251 101.448,42.898 101.678,42.898 v3(101.727,42.85)
NetL401_2: L401.2 La401.2 R401.1 R406.2 | length 16.8
  Layer 1 w0.254: R401.1@25.222,54.229 25.245,54.252 25.88,54.252 v1(25.883,54.254) ; R406.2@32.944,42.113 32.956,42.126 32.956,42.888 v3(32.944,42.901)
  Layer 4 w0.254: v1@25.933,54.229 25.883,54.178 25.883,48.235 30.765,43.352 32.492,43.352 v3(32.944,42.901)
NetQ600_1: Q600.1 Q600.2 Q600.3 Q601.1 Q601.2 Q601.3 R605.2 R606.2 R607.2 | length 5.5
  Layer 6 w0.254: R607.2@93.433,69.38 93.433,69.363 93.706,69.09 R607.2@93.706,69.082 ; R607.2@93.706,69.437 95.308,69.437 95.772,68.973 R605.2@98.397,68.973 R605.2@98.251,68.827
NetQ600_4: Q600.4 R600.1 R602.2 | length 4.9
  Layer 6 w0.254: Q600.4@107.975,66.673 107.977,66.675 108.645,66.675 110.594,64.725 R600.1@110.619,64.725 ; R602.2@110.619,63.168 R600.1@110.619,64.616
NetQ601_4: Q601.4 R601.2 | length 1.9
  Layer 6 w0.254: Q601.4@100.361,66.63 101.883,66.63 102.117,66.864 v1(102.184,66.864)
NetR108_1: R108.1 R110.2 U101.15 | length 2.3
  Layer 1 w0.254: 56.2,32.304 56.376,32.129 56.797,32.129 v3(56.845,32.08)
  Layer 6 w0.254: v3(56.845,32.08) 56.877,32.048 56.877,31.466 R108.1@56.909,31.434 ; R108.1@56.916,31.44 57.802,31.44 R110.2@57.807,31.445
NetR116_2: R116.2 U101.12 | length 7.9
  Layer 1 w0.254: U101.12@54.254,31.953 54.254,30.912 54.788,30.378 56.566,30.378 58.42,32.233 R116.2@60.141,32.233
NetR207_1: R207.1 R210.2 U201.15 | length 3
  Layer 1 w0.254: 80.457,32.207 81.864,32.207 82.171,32.514 82.227,32.514 82.353,32.64 82.353,33.471 R207.1@82.321,33.503
NetR208_2: R208.2 U201.12 | length 5.1
  Layer 1 w0.254: U201.12@78.632,31.708 78.632,31.66 78.638,31.653 78.638,30.836 78.816,30.658 81.254,30.658 82.27,31.674 R208.2@82.398,31.674
NetR307_1: R307.1 R310.2 U301.15 | length 2.9
  Layer 1 w0.254: 102.695,32.207 104.089,32.207 104.398,32.516 104.402,32.516 104.527,32.64 104.578,32.64 104.578,33.471 R307.1@104.546,33.503
NetR308_2: R308.2 U301.12 | length 5.1
  Layer 1 w0.254: U301.12@100.857,31.708 100.857,31.66 100.863,31.653 100.863,30.836 101.041,30.658 103.479,30.658 104.495,31.674 R308.2@104.623,31.674
NetR407_1: R407.1 R410.2 U401.15 | length 3.1
  Layer 1 w0.254: U401.15@33.622,32.257 35.254,32.257 35.615,32.618 35.621,32.618 35.687,32.684 R410.2@35.687,32.69 ; R407.1@35.763,33.604 35.795,33.572 35.795,32.742 R410.2@35.794,32.741
NetR408_2: R408.2 U401.12 | length 5.1
  Layer 1 w0.254: U401.12@32.074,31.809 32.074,31.761 32.08,31.755 32.08,30.937 32.258,30.759 34.696,30.759 35.712,31.775 R408.2@35.839,31.775
NetR500_1: R500.1 TP500.1 | length 4.2
  Layer 1 w0.254: TP500.1@49.936,9.423 50.165,9.652 R500.1@50.165,13.499
NetR501_2: R501.2 TP501.1 | length 4
  Layer 1 w0.254: R501.2@75.209,71.374 75.336,71.501 TP501.1@75.336,75.311
NetR503_1: R503.1 TP502.1 | length 5.5
  Layer 1 w0.254: 12.751,7.341 12.802,7.391 R503.1@12.802,12.711 R503.1@12.802,12.802
NetR504_2: R504.2 TP503.1 | length 4.7
  Layer 1 w0.254: TP503.1@38.989,75.438 38.989,70.866 R504.2@39.065,70.79
PGOOD: J505.5 R107.1 U101.6 | length 66.9
  Layer 1 w0.254: v3(53.238,37.338) 53.248,37.329 53.248,36.222 U101.6@53.25,36.22
  Layer 4 w0.254: v3(53.238,37.338) 53.899,37.998 108.712,37.998 110.591,39.878 J505.5@116.939,39.878
  Layer 6 w0.254: v3(53.238,37.338) 53.246,37.345 54.196,37.345 R107.1@54.229,37.313
SW: L101.1 La101.1 R102.1 U101.7 | length 1.5
  Layer 1 w0.254: v3(50.724,42.189) 50.724,41.578 50.732,41.569 L101.1@50.739,41.569
  Layer 6 w0.254: v3(50.724,42.189) 50.736,42.202 51.307,42.202 51.396,42.291 R102.1@51.562,42.291
SW2: L201.1 La201.1 R202.1 U201.7 | length 1.5
  Layer 1 w0.254: v3(75.26,42.062) 75.26,41.431 75.289,41.402 L201.1@75.432,41.402
  Layer 6 w0.254: v3(75.26,42.062) 75.298,42.025 75.919,42.025 R202.1@75.957,41.987
SW3: L301.1 La301.1 R302.1 U301.7 | length 1.5
  Layer 1 w0.254: L301.1@97.657,41.402 97.688,41.433 v3(97.688,42.062)
  Layer 6 w0.254: v3(97.688,42.062) 97.723,42.028 98.419,42.028 R302.1@98.458,41.989
SW4: L401.1 La401.1 R402.1 U401.7 | length 2.2
  Layer 1 w0.254: L401.1@28.095,41.504 28.798,41.504 28.829,41.535 v3(28.829,42.139)
  Layer 6 w0.254: v3(28.829,42.139) 28.853,42.115 29.651,42.115 R402.1@29.675,42.091
SYNCOUT4: U401.14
